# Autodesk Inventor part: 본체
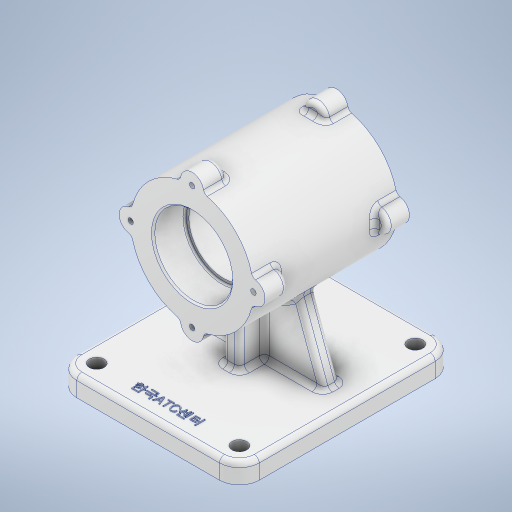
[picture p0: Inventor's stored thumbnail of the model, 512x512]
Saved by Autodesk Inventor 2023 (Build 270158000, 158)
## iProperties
Created: 2023-08
Part Number: 본체
Material: 알루미늄 6061
Document SubType Name: Modeling
Designer: asung
Density: 2.7 g/cm^3
Appearance: 알루미늄 - 평지
Mass: 1215.39 g
Surface Area: 796.917 cm^2
Volume: 450.145 cm^3
Author: asung
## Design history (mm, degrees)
sketch "스케치1"
  geometry: L1 (-43, 65)-(43, 65); L2 (55, 53)-(55, -53); L3 (43, -65)-(-43, -65); L4 (-55, -53)-(-55, 53); L5 (-55, 65)-(55, -65); L6 (55, 65)-(-55, -65); C1 r 4.5 at (43, 53); C2 r 4.5 at (-43, 53); C3 r 4.5 at (-43, -53); C4 r 4.5 at (43, -53); A1 r 12 centre (43, 53) between (55, 53) and (43, 65); A2 r 12 centre (43, -53) between (43, -65) and (55, -53); A3 r 12 centre (-43, -53) between (-55, -53) and (-43, -65); A4 r 12 centre (-43, 53) between (-43, 65) and (-55, 53); 1 further point
  constraints: 12 end point, 8 centre point, 8 point on circle, 8 point on line, 8 tangent, 4 coincident, 3 equal radius, 2 midpoint, 2 parallel, 1 horizontal, 1 perpendicular
  dimensions: "d0" = 110 distance of L5.end L6.end; "d1" = 130 distance of L6.start L5.end; "d2" = 12 radius of A1; "d3" = 9 diameter of C1; "d4" = 9 diameter of C2; "d5" = 9 diameter of C3; "d6" = 9 diameter of C4
extrude "돌출1" new body sketch "스케치1" distance "d7" = 12; taper "d8" = 0 deg
fillet "모깎기1" dims "d9" = 3
node "작업 평면1"
sketch "스케치2"
  geometry: L1 (-9, 12)-(95, 12) reference; L2 (98, 9)-(98, 0) reference; L3 (98, 0)-(-12, 0) reference; L4 (-12, 0)-(-12, 9) reference; L5 (86, 0)-(0, 0) reference; L6 (43, 0)-(43, 82); C1 r 37 at (43, 82); A1 r 3 centre (-9, 9) between (-9, 12) and (-12, 9) reference; A2 r 3 centre (95, 9) between (98, 9) and (95, 12) reference
  constraints: 2 end point, 1 centre point, 1 coincident, 1 vertical
  dimensions: "d14" = 82 distance of L6.start L6.end; "d15" = 37 radius of C1
extrude "돌출2" join sketch "스케치2" stored distance "d16" = 87; taper "d17" = 0 deg
sketch "스케치3"
  geometry: C1 r 37 at (0, 0) reference; C2 r 7 at (0, 37); 2 further points
  constraints: 1 centre point, 1 vertical alignment, 1 other
  dimensions: "d18" = 7 radius of C2
extrude "돌출3" join sketch "스케치3" distance "d19" = 14; taper "d20" = 0 deg
sketch "스케치4"
  geometry: C1 r 37 at (0, 0) reference; C2 r 7 at (0, 37); 2 further points
  constraints: 1 centre point, 1 vertical alignment, 1 other
  dimensions: "d24" = 7 radius of C2
extrude "돌출4" join sketch "스케치4" distance "d25" = 14; taper "d26" = 0 deg
fillet "모깎기2" dims "d30" = 3
fillet "모깎기3" dims "d34" = 3
sketch "스케치5"
  geometry: A1 r 37 centre (43, 82) between (78.863, 91.104) and (52.104, 117.863) reference; 2 further points
  constraints: 1 coincident
hole "구멍1" sketch "스케치5" at (43, 82) diameter "d38" = 42; stored, may be unused: countersink angle "d42" = 90 deg, drill point angle "d44" = 0 deg; dims "d39" = 8, "d40" = 47, "d41" = 19, "d43" = 50
sketch "스케치6"
  geometry: A1 r 37 centre (-43, 82) between (-52.104, 117.863) and (-78.863, 91.104) reference; 2 further points
  constraints: 1 coincident
hole "구멍2" sketch "스케치6" at (-43, 82) diameter "d45" = 42; stored, may be unused: countersink angle "d49" = 90 deg, drill point angle "d51" = 0 deg; dims "d46" = 6, "d47" = 47, "d48" = 19, "d50" = 50
fillet "모깎기4" dims "d52" = 1
chamfer "모따기1" distance "d53" = 1; stored, may be unused: second distance "d54" = 2, angle "d55" = 45 deg
sketch "스케치7"
  geometry: A1 r 7 centre (43, 119) between (49.889, 120.239) and (36.111, 120.239) reference; A2 r 7 centre (6, 82) between (4.761, 88.889) and (4.761, 75.111) reference; A3 r 7 centre (80, 82) between (81.239, 75.111) and (81.239, 88.889) reference; A4 r 7 centre (43, 45) between (36.111, 43.761) and (49.889, 43.761) reference; 5 further points
  constraints: 4 coincident
hole "구멍3" sketch "스케치7" at (43, 119), (6, 82), (80, 82), (43, 45) diameter "d56" = 3.242; stored, may be unused: countersink angle "d60" = 90 deg, drill point angle "d62" = 118 deg; dims "d57" = 8, "d58" = 47, "d59" = 19, "d61" = 10
sketch "스케치8"
  geometry: A1 r 7 centre (-43, 119) between (-36.111, 120.239) and (-49.889, 120.239) reference; A2 r 7 centre (-6, 82) between (-4.761, 75.111) and (-4.761, 88.889) reference; A3 r 7 centre (-43, 45) between (-49.889, 43.761) and (-36.111, 43.761) reference; A4 r 7 centre (-80, 82) between (-81.239, 88.889) and (-81.239, 75.111) reference; 5 further points
  constraints: 4 coincident
hole "구멍4" sketch "스케치8" at (-43, 119), (-6, 82), (-43, 45), (-80, 82) diameter "d63" = 3.242; stored, may be unused: countersink angle "d67" = 90 deg, drill point angle "d69" = 118 deg; dims "d64" = 8, "d65" = 4, "d66" = 2, "d68" = 10
sketch "스케치9"
  geometry: L1 (52, -53)-(52, 53) reference; L2 (43, 62)-(-43, 62) reference; L3 (-52, 53)-(-52, -53) reference; L4 (-43, -62)-(43, -62) reference; L5 (-5, -15)-(5, -15); L6 (5, -15)-(5, 25); L7 (5, 25)-(-5, 25); L8 (-5, 25)-(-5, -15); L9 (-43, -65)-(43, -65) reference; L10 (-55, 53)-(-55, -53) reference; C1 r 4.5 at (-43, -53) reference; C2 r 4.5 at (43, -53) reference; C3 r 4.5 at (43, 53) reference; C4 r 4.5 at (-43, 53) reference; A1 r 9 centre (43, -53) between (43, -62) and (52, -53) reference; A2 r 9 centre (43, 53) between (52, 53) and (43, 62) reference; A3 r 9 centre (-43, 53) between (-43, 62) and (-52, 53) reference; A4 r 9 centre (-43, -53) between (-52, -53) and (-43, -62) reference; 3 further points
  constraints: 8 end point, 2 midpoint, 2 parallel, 1 horizontal, 1 perpendicular
  dimensions: "d70" = 10 distance of L7.end L6.end; "d71" = 40 distance of L6.end L5.end; "d72" = 70 distance from line of point (-5, 5) L9; "d73" = 55 distance from line of point (0, 25) L10
extrude "돌출5" join sketch "스케치9" stored distance "d74" = 14; taper "d75" = 0 deg
node "작업 평면4"
sketch "스케치10"
  geometry: L1 (-9, 12)-(38, 12) reference; L2 (38, 12)-(38, 45.339) reference; L3 (48, 45.339)-(48, 12) reference; L4 (48, 12)-(95, 12) reference; L5 (98, 9)-(98, 0) reference; L6 (98, 0)-(-12, 0) reference; L7 (-12, 0)-(-12, 9) reference; L8 (0, 12)-(86, 12) reference; L9 (2, 12)-(19.586, 60.316); L10 (84, 12)-(67.029, 58.627); C1 r 21 at (43, 82) reference; A1 r 3 centre (-9, 9) between (-9, 12) and (-12, 9) reference; A2 r 37 centre (43, 82) between (48, 45.339) and (38, 45.339) reference; A3 r 3 centre (95, 9) between (98, 9) and (95, 12) reference; 2 further points
  constraints: 4 end point, 2 point on line, 1 midpoint
  dimensions: "d76" = 14 distance from line of L9.start L7; "d77" = 14 horizontal distance of L10.start point (98, 4.5); "d78" = 110 deg angle of L10 L4; "d79" = 110 deg angle of L9 L1
  node "절단 모서리 투영3"
feature "리브1" dims "d80" = 1, "d81" = 10, "d82" = 0, "d83" = 0, "d84" = 1, "d85" = 1
feature "리브2" dims "d86" = 1, "d87" = 10, "d88" = 0, "d89" = 0, "d90" = 1, "d91" = 1
fillet "모깎기5" dims "d92" = 3
fillet "모깎기6" dims "d93" = 3
sketch "스케치11"
  geometry: L1 (55, -53)-(55, 53) reference; L2 (40.282, 7)-(40.282, 3) reference; L3 (-36.716, -3)-(-8, -3) reference; L4 (-8, -3)-(-8, -12) reference; L5 (-2, -18)-(2, -18) reference; L6 (8, -12)-(8, -3) reference; L7 (8, -3)-(36.716, -3) reference; L8 (43.101, 3)-(43.101, 7) reference; L9 (36.716, 13)-(8, 13) reference; L10 (8, 13)-(8, 22) reference; L11 (2, 28)-(-2, 28) reference; L12 (-8, 22)-(-8, 13) reference; L13 (-8, 13)-(-36.716, 13) reference; L14 (-43.101, 7)-(-43.101, 3) reference; L15 (52, -53)-(52, 53) reference; L16 (43, 62)-(-43, 62) reference; L17 (-52, 53)-(-52, -53) reference; L18 (-43, -62)-(43, -62) reference; C1 r 4.5 at (-43, -53) reference; C2 r 4.5 at (43, -53) reference; C3 r 4.5 at (43, 53) reference; C4 r 4.5 at (-43, 53) reference; A1 r 6 centre (-2, -12) between (-8, -12) and (-2, -18) reference; A2 r 6 centre (2, -12) between (2, -18) and (8, -12) reference; A3 r 6 centre (2, 22) between (8, 22) and (2, 28) reference; A4 r 6 centre (-2, 22) between (-2, 28) and (-8, 22) reference; A5 r 9 centre (43, -53) between (43, -62) and (52, -53) reference; A6 r 9 centre (43, 53) between (52, 53) and (43, 62) reference; A7 r 9 centre (-43, 53) between (-43, 62) and (-52, 53) reference; A8 r 9 centre (-43, -53) between (-52, -53) and (-43, -62) reference; 5 further points
  constraints: 3 midpoint, 1 vertical alignment, 5 other
  dimensions: "d98" = 58 vertical distance of point (0, -53) point (40.282, 5)
feature "엠보싱1" sketch "스케치11" dims "d0" = 110, "d1" = 130, "d2" = 12, "d3" = 9, "d4" = 9, "d5" = 9, "d6" = 9, "d96" = 0.5, "d97" = 0
feature "ѡ耀ѣ耀ѥ耀ѧ耀ѩ耀ѫ耀ѭ耀ѯ耀" dims "d0" = 110, "d1" = 130, "d2" = 12, "d3" = 9, "d4" = 9, "d5" = 9, "d6" = 9, "d7" = 12, "d8" = 0, "d9" = 3, "d10" = -70, "d14" = 82, "d15" = 37, "d16" = 87, "d17" = 0, "d18" = 7, "d19" = 14, "d20" = 0, "d21" = 40, "d22" = 360 deg, "d24" = 7, "d25" = 14, "d26" = 0, "d27" = 40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
node "솔리드1"
pattern_circular "원형 패턴1" dims angle "d22" = 360 deg
pattern_circular "원형 패턴2" dims angle "d28" = 360 deg
pattern_circular "원형 패턴3" dims angle "d32" = 360 deg
pattern_circular "원형 패턴4" dims angle "d36" = 360 deg
node "투영된 루프1"
node "투영된 루프2"
node "절단 모서리 투영1"
node "절단 모서리 투영2"
node "절단 모서리 투영4"
feature "A9D066F2-1C7D-4E18-AEED-F7BC21143FA4" dims "d38" = 42, "d39" = 8, "d40" = 47, "d41" = 19, "d42" = 90 deg, "d43" = 50, "d44" = 0
